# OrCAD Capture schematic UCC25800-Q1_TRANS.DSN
size Custom; title: UCC25800-Q1 Ultra-low EMI Transformer Driver; rev: 1.0; note: Datasheet:SLUSDX3B    EVM:SLUUCE8A; note: Synchronous Step Down Converter
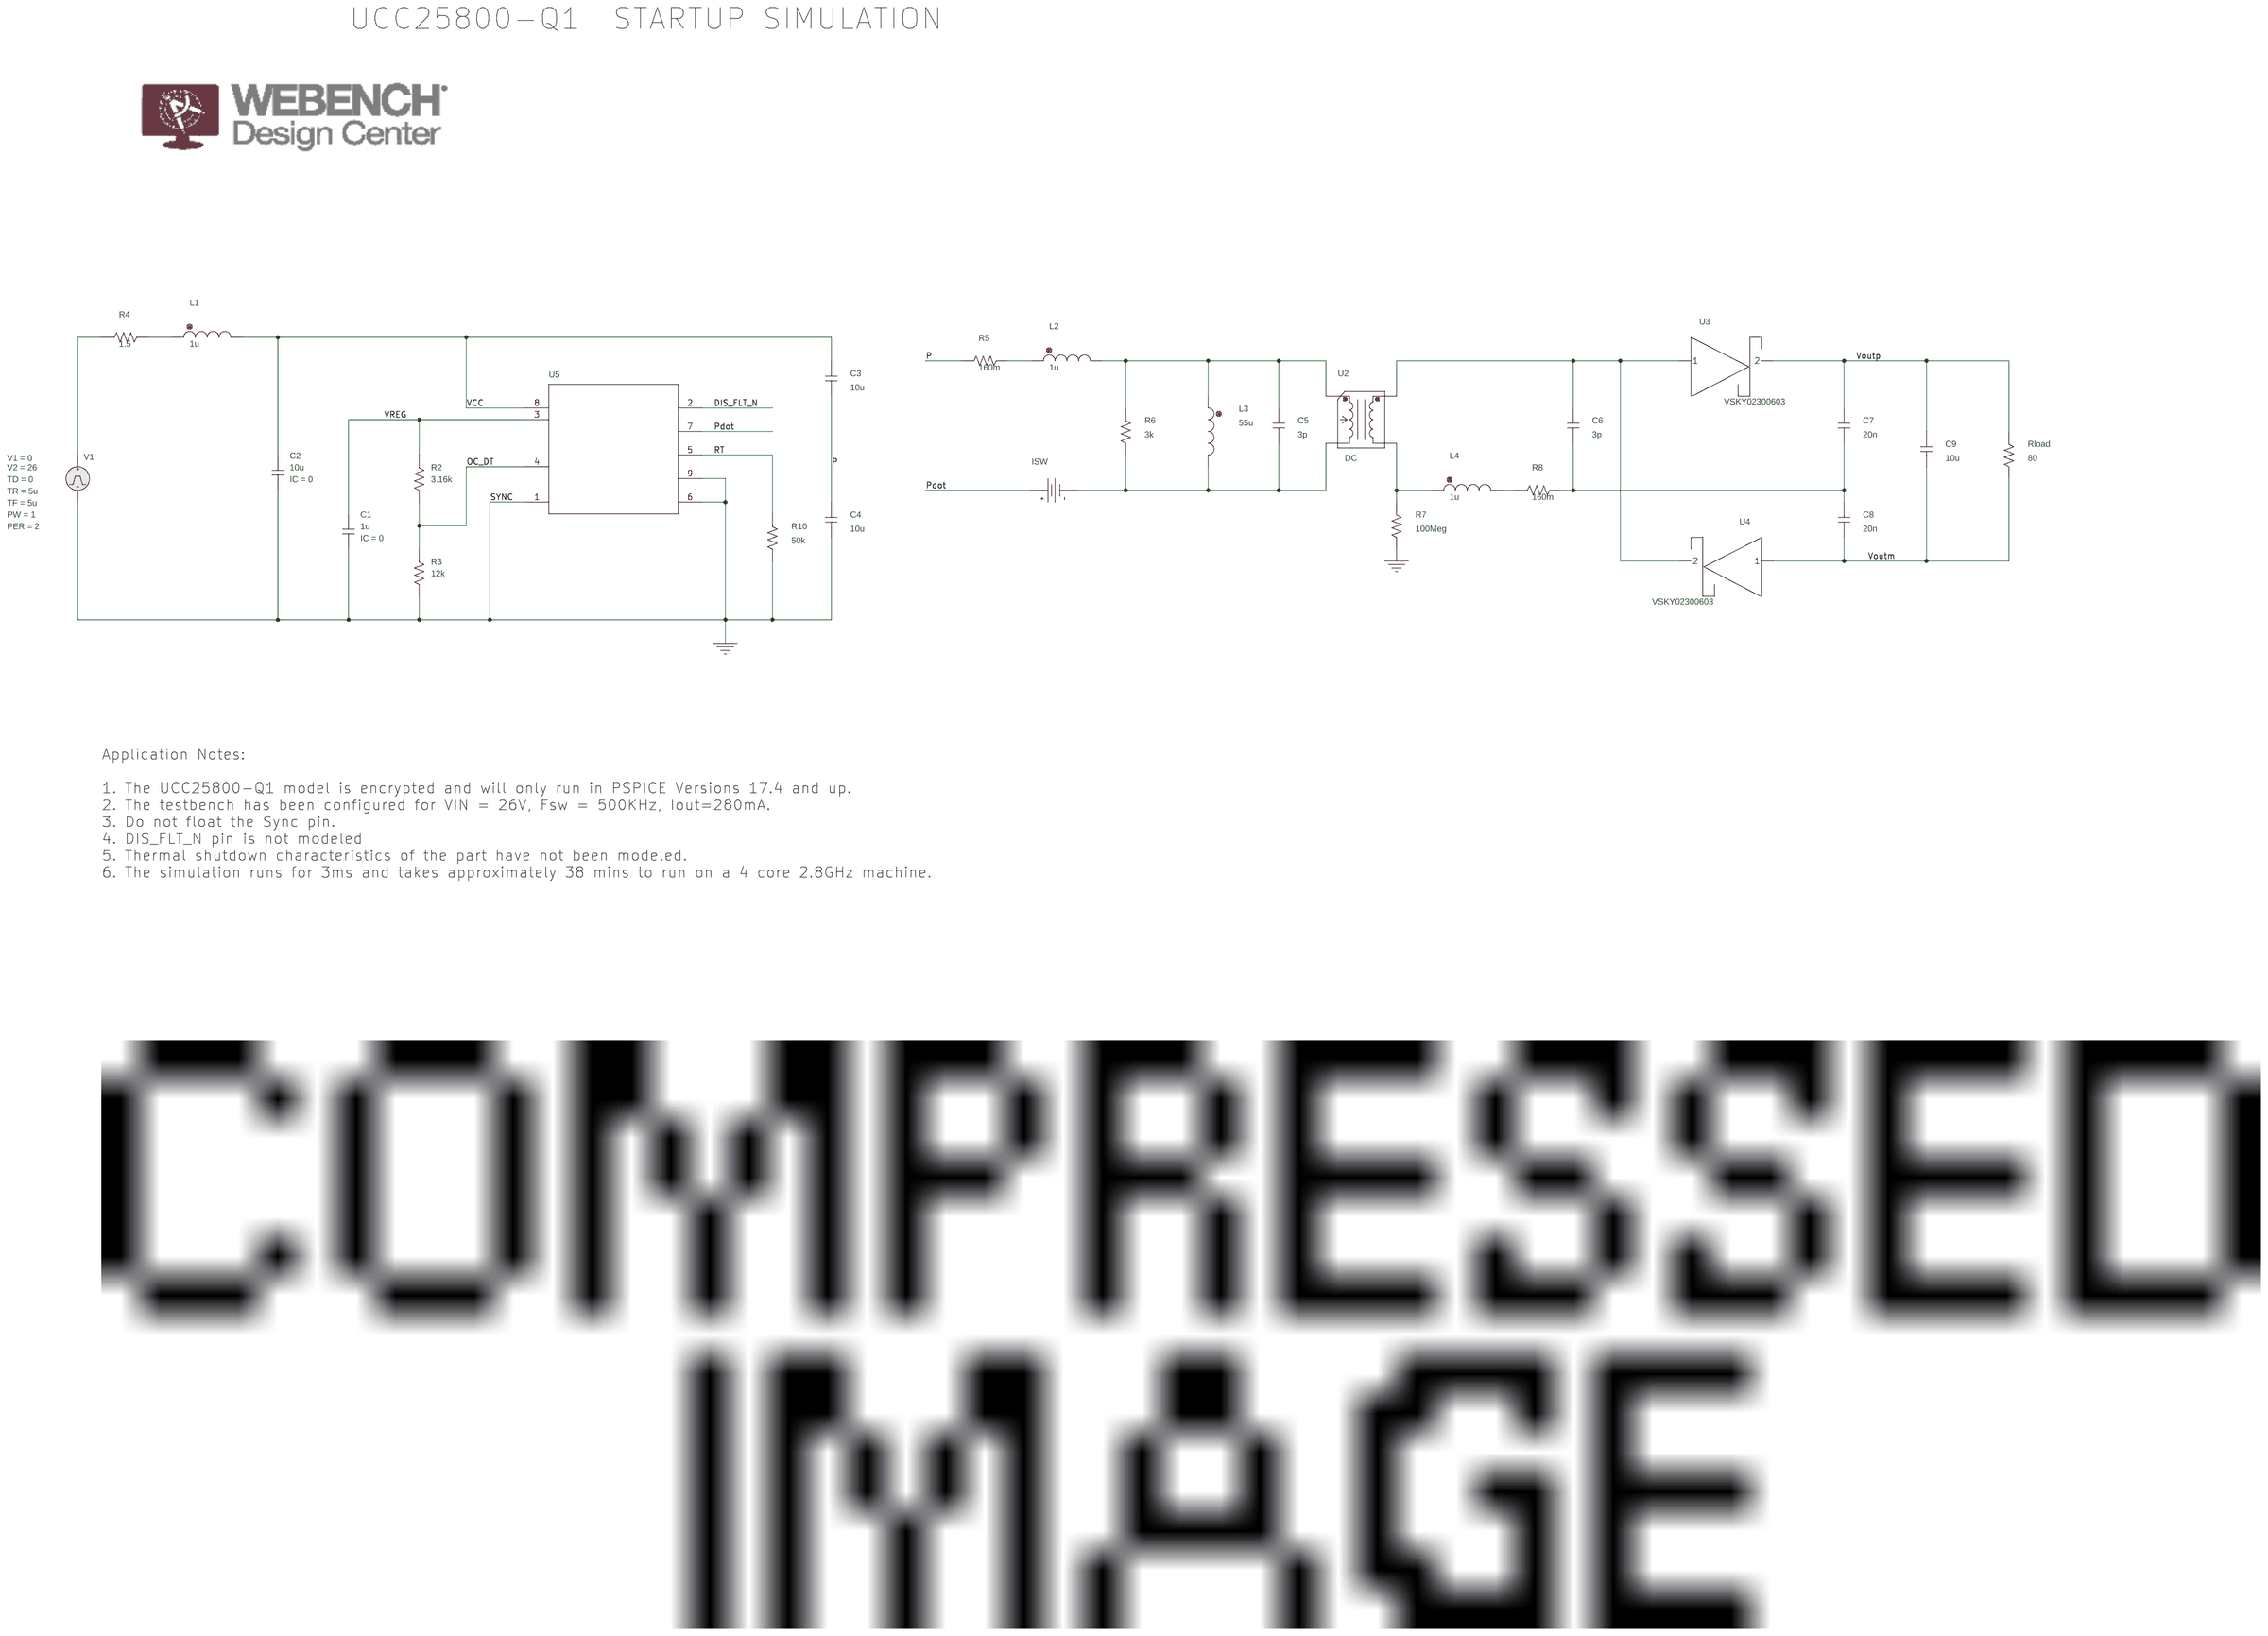
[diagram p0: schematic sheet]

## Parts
C1  1u  [cap196]
C2  10u  [cap196]
C3  10u  [cap196]
C4  10u  [cap196]
C5  3p  [cap196]
C6  3p  [cap196]
C7  20n  [cap196]
C8  20n  [cap196]
C9  10u  [cap196]
ISW  VDC
L1  1u  [DISC350x175LS200x100034]
L2  1u  [DISC350x175LS200x100034]
L3  55u  [DISC350x175LS200x100034]
L4  1u  [DISC350x175LS200x100034]
R2  3.16k  [AXRC05]
R3  12k  [AXRC05]
R4  1.5  [AXRC05]
R5  160m  [AXRC05]
R6  3k  [AXRC05]
R7  100Meg  [AXRC05]
R8  160m  [AXRC05]
R10  50k  [AXRC05]
Rload  80  [AXRC05]
U2  DC
U3  VSKY02300603
U4  VSKY02300603
U5  Value
V1  VPULSE

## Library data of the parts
C1 C2 = C: IC: 0
C3-C9 = C
ISW = VDC
L1-L4 = L
R2-R8 R10 Rload = R
U2 = DC
U3 = VSKY02300603_1
U4 = VSKY02300603
U5 = UCC25800-Q1DGN_TRANS
V1 = VPULSE: PER: 2; PW: 1; TD: 0; TF: 5u; TR: 5u; V1: 0; V2: 26

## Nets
VCC: C2.1 C3.1 L1.2 U5.8(VCC)
0: C1.2 C2.2 C4.2 R3.2 R7.2 R10.2 U5.1(SYNC) U5.6(GND) U5.9(EP) V1.2(-)
DIS_FLT_N: U5.2(DIS_FLT_N)
OC_DT: R2.2 R3.1 U5.4(OC_DT)
P: C3.2 C4.1 R5.1
Pdot: ISW.0(+) U5.7(SW)
RT: R10.1 U5.5(RT)
Voutm: C8.2 C9.2 Rload.2 U4.1
Voutp: C7.1 C9.1 Rload.1 U3.2
VREG: C1.1 R2.1 U5.3(VREG)
N98742: R4.1 V1.1(+)
N98752: L1.1 R4.2
N98878: L2.1 R5.2
N98884: C5.2 L2.2 L3.1 R6.1 U2.1(A)
N98918: C6.2 U2.3(D) U3.1 U4.2
N99174: C5.1 ISW.1(-) L3.2 R6.2 U2.2(B)
N99182: L4.1 R7.1 U2.4(C)
N99188: C6.1 C7.2 C8.1 R8.2
N99446: L4.2 R8.1

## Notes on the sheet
- UCC25800-Q1  STARTUP SIMULATION
- Application Notes:
  1. The UCC25800-Q1 model is encrypted and will only run in PSPICE Versions 17.4 and up.
  2. The testbench has been configured for VIN = 26V, Fsw = 500KHz, Iout=280mA.
  3. Do not float the Sync pin.
  4. DIS_FLT_N pin is not modeled
  5. Thermal shutdown characteristics of the part have not been modeled.
  6. The simulation runs for 3ms and takes approximately 38 mins to run on a 4 core 2.8GHz machine.
